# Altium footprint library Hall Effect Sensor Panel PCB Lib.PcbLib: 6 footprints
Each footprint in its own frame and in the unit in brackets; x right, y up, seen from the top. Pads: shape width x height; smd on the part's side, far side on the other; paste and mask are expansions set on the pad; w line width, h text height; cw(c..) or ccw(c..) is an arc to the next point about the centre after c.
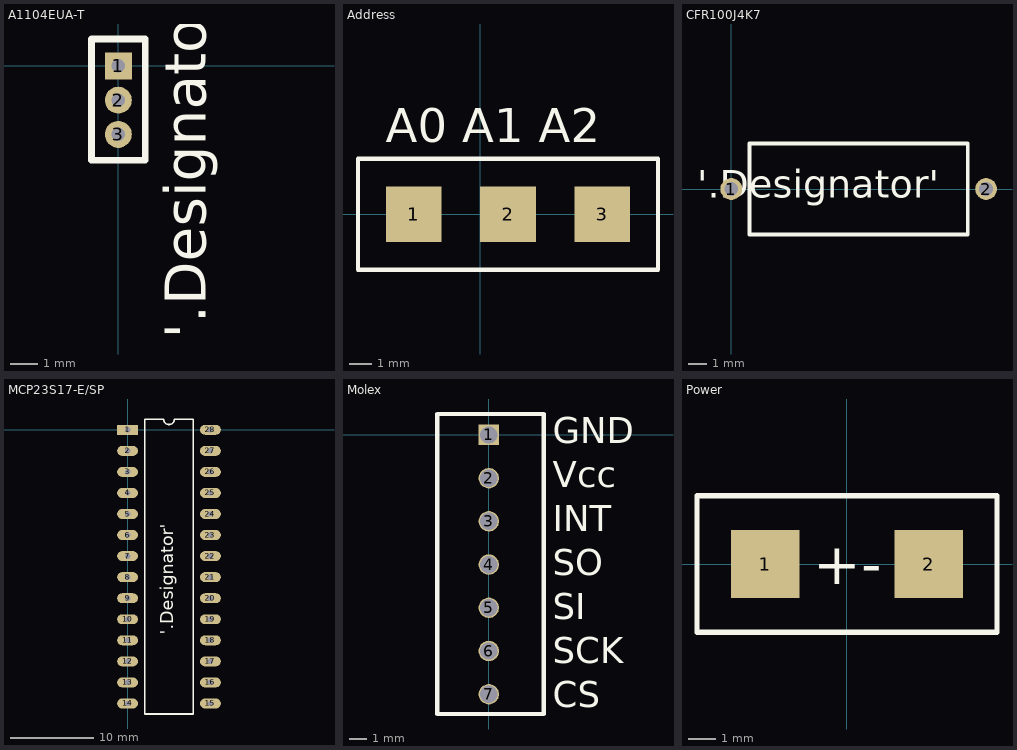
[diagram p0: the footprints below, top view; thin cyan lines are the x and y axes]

## A1104EUA-T [mm]
pads (3):
  rect 1x1 hole 0.5: 1(0,0)
  round 1 hole 0.5: 2(0,-1.27) 3(0,-2.54)
Top Overlay:
  lines w0.254: -1,-3.5 -1,1 1,1 1,-3.5 -1,-3.5
  text "'.Designator'" at 3.238,-10.133 h1.52

## Address [mm]
pads (3):
  rect 2.5x2.5 smd: 1(-3,0) 2(1.25,0) 3(5.5,0)
Top Overlay:
  lines w0.2: -5.5,-2.5 -5.5,0 -5.5,2.5 8,2.5 8,-2.5 -5.5,-2.5
  text "A0 A1 A2" at -4.246,3.254 h1.52

## CFR100J4K7 [mm]
pads (2):
  round 1.2 hole 0.76: 1(0,0) 2(14,0)
Top Overlay:
  lines w0.2: 1,-2.5 13,-2.5 13,2.5 1,2.5 1,0 1,-2.5
  text "'.Designator'" at -1.883,-0.488 h1.52

## MCP23S17-E/SP [mm]
pads (28):
  rect 2.5x1.2 hole 0.65: 1(0,0)
  oval 2.5x1.2 hole 0.65: 2(0,-2.54) 3(0,-5.08) 4(0,-7.62) 5(0,-10.16) 6(0,-12.7) 7(0,-15.24) 8(0,-17.78) 9(0,-20.32) 10(0,-22.86) 11(0,-25.4) 12(0,-27.94) 13(0,-30.48) 14(0,-33.02) 15(10,-33.02) 16(10,-30.48) 17(10,-27.94) 18(10,-25.4) 19(10,-22.86) 20(10,-20.32) 21(10,-17.78) 22(10,-15.24) 23(10,-12.7) 24(10,-10.16) 25(10,-7.62) 26(10,-5.08) 27(10,-2.54) 28(10,0)
Top Overlay:
  lines w0.2: 2.085,-34.29 7.915,-34.29 7.915,1.27 5.635,1.27 cw(c5,1.27) 4.365,1.27 2.085,1.27 2.085,-34.29
  text "'.Designator'" at 5.538,-24.746 h1.52

## Molex [mm]
pads (7):
  rect 1.2x1.2 hole 1.02: 1(0,0)
  round 1.2 hole 1.02: 2(0,-2.54) 3(0,-5.08) 4(0,-7.62) 5(0,-10.16) 6(0,-12.7) 7(0,-15.24)
Top Overlay:
  lines w0.254: -3.025,-16.4 3.225,-16.4 3.225,1.23 -3.025,1.23 -3.025,-16.4
  text "INT" at 3.754,-5.663 h1.52
  text "SO" at 3.754,-8.246 h1.52
  text "Vcc" at 3.754,-3.079 h1.52
  text "GND" at 3.754,-0.496 h1.52
  text "CS" at 3.754,-15.996 h1.52
  text "SCK" at 3.754,-13.413 h1.52
  text "SI" at 3.754,-10.829 h1.52

## Power [mm]
pads (2):
  rect 2.5x2.5 smd: 1(-3,0) 2(3,0)
Top Overlay:
  lines w0.2: -5.5,-2.5 5.5,-2.5 5.5,2.5 -5.5,2.5 -5.5,0 -5.5,-2.5
  text "+-" at -1.246,-0.75 h1.52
